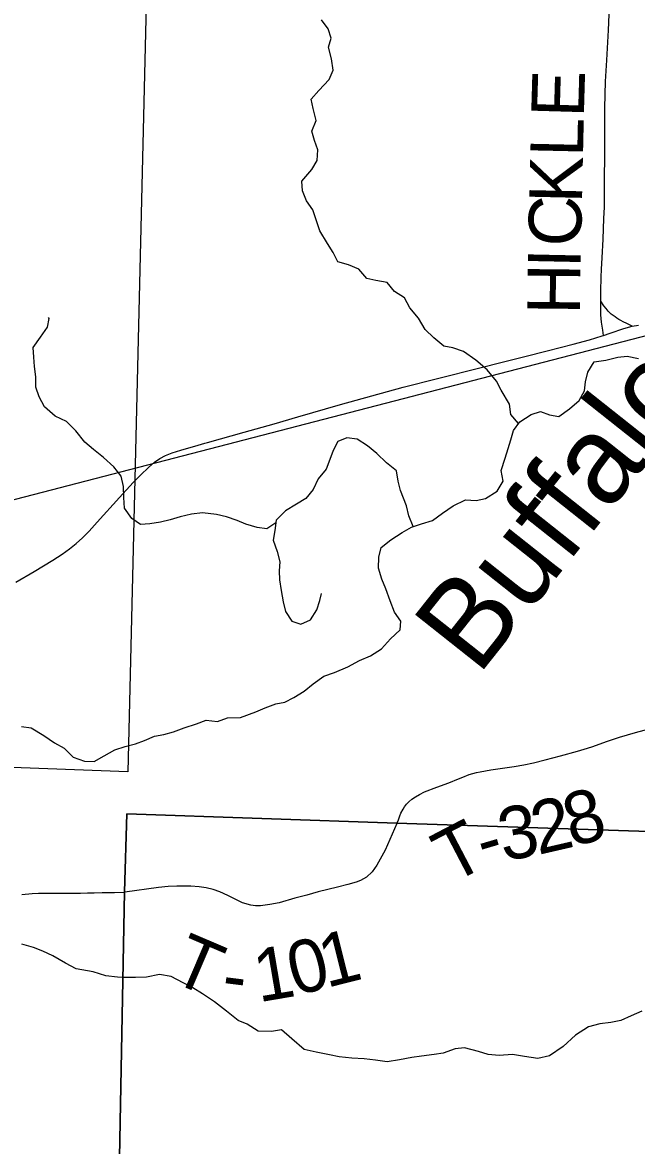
# Model space of a CAD drawing. Extents: x 0 to 34, y 0 to 22.
# Drawn here: x 26.994 to 27.656, y 18.296 to 19.507 of the extents above; entities that cross this region are included whole.
import ezdxf

# ---------------------------------------------------------------- set-up
doc = ezdxf.new("R2010")
doc.units = 0
for name, color, linetype in [('GM_X_Corporation', 7, 'Continuous'), ('GM_X_Minor_River', 7, 'Continuous'), ('GM_X_Minor_River_Text', 7, 'Continuous'), ('GM_X_Rail_Line', 7, 'Continuous'), ('GM_X_State_Route', 7, 'Continuous'), ('GM_X_Township_Road', 7, 'Continuous'), ('GM_X_Township_Road_Text', 7, 'Continuous')]:
    doc.layers.add(name, color=color, linetype=linetype)

msp = doc.modelspace()

# ---------------------------------------------------------------- linework, layer by layer
at = {"layer": 'GM_X_Corporation'}
for points in [[(26.6535, 14.621), (27.01, 14.6164), (27.046, 14.6155), (27.043, 14.755), (27.052, 15.403), (27.0676, 16.5549), (27.0694, 16.6556), (27.0775, 16.888), (27.0944, 18.0731), (27.1039, 18.5696), (27.1064, 18.6537), (27.3971, 18.6436), (28.3421, 18.6121), (28.7772, 18.6028), (29.0074, 18.5935), (29.6561, 18.5791), (29.6772, 18.5786), (30.101, 18.5701), (30.3167, 18.565), (30.3167, 20.9), (23.5167, 20.9)], [(26.3378, 16.673), (27.0694, 16.6556), (27.0775, 16.888), (27.0944, 18.0731), (27.1039, 18.5696), (27.1064, 18.6537), (27.3971, 18.6436), (28.3421, 18.6121), (28.7772, 18.6028), (29.0074, 18.5935), (29.6561, 18.5791), (29.6772, 18.5786), (30.101, 18.5701), (30.3167, 18.565), (30.3167, 20.9), (25.1014, 20.9)], [(23.5167, 14.1), (30.3167, 14.1), (30.3167, 18.565), (30.101, 18.5701), (29.6772, 18.5786), (29.6561, 18.5791), (29.0074, 18.5935), (28.7772, 18.6028), (28.3421, 18.6121), (27.3971, 18.6436), (27.1064, 18.6537), (27.1039, 18.5696), (27.0944, 18.0731), (27.0775, 16.888), (27.0694, 16.6556), (27.0676, 16.5549), (27.052, 15.403), (27.043, 14.755), (27.046, 14.6155), (27.01, 14.6164), (26.6535, 14.621)], [(30.3167, 14.5373), (30.3167, 18.565), (30.101, 18.5701), (29.6772, 18.5786), (29.6561, 18.5791), (29.0074, 18.5935), (28.7772, 18.6028), (28.3421, 18.6121), (27.3971, 18.6436), (27.1064, 18.6537), (27.1039, 18.5696), (27.0944, 18.0731)]]:
    msp.add_lwpolyline(points, dxfattribs=at)
msp.add_lwpolyline([(27.1321, 19.6957), (27.1305, 19.6616), (27.1072, 18.6988), (26.0916, 18.7368), (26.1009, 19.7362)], close=True, dxfattribs=at)
at = {"layer": 'GM_X_Minor_River'}
for points in [[(27.5284, 19.0744), (27.52, 19.0842), (27.5187, 19.0952), (27.5095, 19.1102), (27.5045, 19.12), (27.4946, 19.1324), (27.4824, 19.1429), (27.4691, 19.1522), (27.4577, 19.1559), (27.4479, 19.1577), (27.4372, 19.1667), (27.4277, 19.1757), (27.4204, 19.1881), (27.4112, 19.199), (27.4055, 19.2099), (27.3948, 19.2166), (27.3868, 19.2264), (27.3747, 19.2285), (27.3648, 19.2307), (27.3564, 19.2408), (27.3451, 19.2456), (27.3337, 19.2489), (27.3287, 19.2587), (27.3226, 19.2685), (27.3141, 19.2821), (27.3106, 19.293), (27.3067, 19.3047), (27.2999, 19.3145), (27.2956, 19.3254), (27.2948, 19.3356), (27.3056, 19.3483), (27.3112, 19.3582), (27.3122, 19.3696), (27.3084, 19.3797), (27.3056, 19.3896), (27.3104, 19.401), (27.3069, 19.4142), (27.3049, 19.424), (27.3132, 19.4336), (27.3244, 19.4455), (27.3285, 19.4554), (27.3269, 19.4675), (27.3237, 19.4803), (27.3263, 19.4898), (27.3232, 19.5), (27.3159, 19.5098)], [(27.267, 18.9674), (27.2572, 18.9609), (27.2466, 18.9623), (27.2345, 18.966), (27.225, 18.9697), (27.2136, 18.9737), (27.203, 18.9763), (27.1879, 18.978), (27.1758, 18.9767), (27.1637, 18.9739), (27.1528, 18.9704), (27.1426, 18.968), (27.1309, 18.9664), (27.1211, 18.9655), (27.1116, 18.9719), (27.1039, 18.9832), (27.1031, 18.9945), (27.1026, 19.0066), (27.1002, 19.0176), (27.0922, 19.0277), (27.0811, 19.0379), (27.0705, 19.0465), (27.061, 19.0543), (27.0514, 19.0667), (27.0411, 19.0765), (27.029, 19.0824), (27.0175, 19.0925), (27.0118, 19.1031), (27.0083, 19.1136), (27.0082, 19.1246), (27.0069, 19.136), (27.0061, 19.1458), (27.0053, 19.1564), (27.0131, 19.1675), (27.0206, 19.1782), (27.0224, 19.1877), (27.022, 19.1888)], [(27.0933, 18.7224), (27.1043, 18.7263), (27.1156, 18.7291), (27.1254, 18.7326), (27.1359, 18.7372), (27.1461, 18.7392), (27.1567, 18.742), (27.168, 18.7463), (27.1812, 18.7506), (27.1917, 18.7545), (27.2038, 18.7531), (27.2148, 18.757), (27.2287, 18.7575), (27.2453, 18.7634), (27.2555, 18.768), (27.2668, 18.7723), (27.2766, 18.774), (27.2864, 18.779), (27.2973, 18.7859), (27.307, 18.7936), (27.3187, 18.8021), (27.33, 18.806), (27.3443, 18.8122), (27.3571, 18.8188), (27.3688, 18.8238), (27.3808, 18.8315), (27.3905, 18.8422), (27.4007, 18.8518), (27.4017, 18.8613), (27.3948, 18.8711), (27.3902, 18.8831), (27.3855, 18.896), (27.3809, 18.9065), (27.3774, 18.9186), (27.3777, 18.9304), (27.3802, 18.9406), (27.3907, 18.9491), (27.4028, 18.9568), (27.4129, 18.9626), (27.4239, 18.9661), (27.4355, 18.97), (27.4464, 18.9777), (27.4581, 18.9858), (27.4713, 18.992), (27.4826, 18.9913), (27.4928, 18.9937), (27.5052, 19.0014), (27.5119, 19.0121), (27.5095, 19.0238), (27.514, 19.0371), (27.5173, 19.0474), (27.5202, 19.0569), (27.5228, 19.0668), (27.5299, 19.0763), (27.5419, 19.084), (27.5521, 19.0872), (27.5619, 19.0839), (27.5718, 19.0821), (27.5834, 19.0902), (27.5936, 19.0994), (27.5995, 19.1097), (27.6006, 19.1195), (27.6031, 19.1298), (27.6098, 19.1408), (27.6223, 19.1429), (27.6355, 19.146), (27.6453, 19.1469), (27.6578, 19.1444)], [(27.4149, 18.9632), (27.4102, 18.975), (27.4078, 18.9856), (27.4012, 19.0022), (27.3985, 19.0124), (27.3969, 19.0234), (27.3862, 19.032), (27.3756, 19.0421), (27.3657, 19.0503), (27.3546, 19.0574), (27.3433, 19.0588), (27.3335, 19.0549), (27.3287, 19.0454), (27.325, 19.0355), (27.3209, 19.0252), (27.3123, 19.0149), (27.3071, 19.0031), (27.2993, 18.9936), (27.2891, 18.9874), (27.2774, 18.9801), (27.2673, 18.9701), (27.2659, 18.9591), (27.2641, 18.9485), (27.2684, 18.9364), (27.2711, 18.9254), (27.2705, 18.9156), (27.2709, 18.9057), (27.2725, 18.8944), (27.2749, 18.8823), (27.2773, 18.8717), (27.2842, 18.8612), (27.2936, 18.8579), (27.3042, 18.8629), (27.3109, 18.8736), (27.3142, 18.8835), (27.316, 18.8911)], [(26.9929, 18.7478), (27.0032, 18.7461), (27.0168, 18.7379), (27.0283, 18.73), (27.0389, 18.7245), (27.0484, 18.7147), (27.0606, 18.7103), (27.0711, 18.71), (27.0817, 18.7162), (27.0933, 18.7224)], [(27.0963, 18.4775), (27.0836, 18.479), (27.0701, 18.4831), (27.0515, 18.4863), (27.0402, 18.4926), (27.0265, 18.5004), (27.0158, 18.5056), (27.0056, 18.5093), (26.9931, 18.5129)], [(27.6611, 18.4406), (27.6497, 18.4357), (27.6387, 18.4308), (27.6278, 18.4286), (27.616, 18.4271), (27.6039, 18.4237), (27.5896, 18.415), (27.5763, 18.4025), (27.5619, 18.3926), (27.549, 18.3896), (27.5347, 18.3919), (27.5218, 18.3942), (27.5075, 18.3931), (27.4957, 18.3939), (27.4851, 18.3973), (27.47, 18.4011), (27.4602, 18.4), (27.4473, 18.3954), (27.4375, 18.3939), (27.4239, 18.3924), (27.4133, 18.3909), (27.4001, 18.3883), (27.3868, 18.386), (27.3743, 18.3879), (27.3619, 18.3895), (27.3486, 18.3899), (27.335, 18.3914), (27.3248, 18.3937), (27.3104, 18.3964), (27.2972, 18.3994), (27.284, 18.4108), (27.2731, 18.4207), (27.2621, 18.4188), (27.2477, 18.4192), (27.236, 18.4268), (27.2262, 18.4306), (27.2137, 18.4408), (27.2009, 18.4507), (27.1877, 18.4594), (27.1775, 18.4659), (27.1669, 18.4712), (27.1541, 18.4781), (27.1416, 18.4804), (27.1276, 18.4773), (27.1155, 18.477), (27.103, 18.477), (27.0963, 18.4775)]]:
    msp.add_lwpolyline(points, dxfattribs=at)
at = {"layer": 'GM_X_Rail_Line'}
msp.add_lwpolyline([(28.8018, 19.5008), (28.2457, 19.3243), (28.1529, 19.2955), (27.3181, 19.0787), (26.8719, 18.963)], dxfattribs=at)
at = {"layer": 'GM_X_State_Route'}
msp.add_lwpolyline([(26.9866, 18.9032), (27.0064, 18.915), (27.0266, 18.9271), (27.0365, 18.9335), (27.0445, 18.9393), (27.0517, 18.9451), (27.0586, 18.9513), (27.0656, 18.9583), (27.0744, 18.9679), (27.0984, 18.9948), (27.1131, 19.0108), (27.1209, 19.0188), (27.1299, 19.0275), (27.1361, 19.0328), (27.1418, 19.0367), (27.148, 19.04), (27.155, 19.0427), (27.1644, 19.0458), (27.183, 19.051), (27.1902, 19.0531), (27.1932, 19.054), (27.2326, 19.0651), (27.2649, 19.0742), (27.2906, 19.0815), (27.3366, 19.0949), (27.4042, 19.1137), (27.441, 19.1231), (27.4868, 19.1344), (27.5109, 19.1404), (27.535, 19.1466), (27.5591, 19.1527), (27.5874, 19.1598), (27.6048, 19.1646), (27.6184, 19.1688), (27.6198, 19.1693), (27.6272, 19.1718), (27.6419, 19.1769), (27.6507, 19.1793), (27.6577, 19.1806)], dxfattribs=at)
at = {"layer": 'GM_X_Township_Road'}
for points in [[(27.6169, 19.2065), (27.6169, 19.2172), (27.6174, 19.2321), (27.6179, 19.2408), (27.6184, 19.2532), (27.6196, 19.2731), (27.6204, 19.2954), (27.6209, 19.3078), (27.6211, 19.3265), (27.6213, 19.375), (27.6214, 19.3893), (27.6215, 19.4147), (27.6222, 19.4433), (27.6234, 19.4663), (27.6252, 19.4986), (27.6268, 19.5327)], [(27.6198, 19.1693), (27.6191, 19.1749), (27.6179, 19.1836), (27.6172, 19.1917), (27.6169, 19.2023), (27.6169, 19.2065)], [(27.6507, 19.1793), (27.6451, 19.1822), (27.6413, 19.1842), (27.6388, 19.1855), (27.6365, 19.1867), (27.6344, 19.1879), (27.6324, 19.1893), (27.6303, 19.1908), (27.6283, 19.1924), (27.6251, 19.1955), (27.6227, 19.1983), (27.6204, 19.2014), (27.6169, 19.2065)], [(27.3973, 18.6431), (27.3989, 18.6472), (27.4006, 18.6512), (27.4017, 18.6541), (27.4039, 18.6584), (27.4055, 18.661), (27.4077, 18.6638), (27.4102, 18.6664), (27.4134, 18.6692), (27.4174, 18.672), (27.4217, 18.6744), (27.4272, 18.6771), (27.4405, 18.6823), (27.4492, 18.6856), (27.455, 18.6878), (27.4619, 18.6906), (27.4682, 18.6931), (27.4751, 18.6958), (27.4792, 18.6971), (27.483, 18.698), (27.487, 18.6989), (27.4985, 18.701), (27.5236, 18.7047), (27.534, 18.7064), (27.5444, 18.7085), (27.557, 18.7116), (27.5736, 18.7161), (27.592, 18.7211), (27.6027, 18.7242), (27.6084, 18.7262), (27.623, 18.7314), (27.6371, 18.7361), (27.6543, 18.7413), (27.6693, 18.7453)], [(27.3973, 18.6431), (27.3847, 18.6142), (27.3755, 18.598), (27.3706, 18.5909), (27.3644, 18.5851), (27.358, 18.5816), (27.3534, 18.5797), (27.3444, 18.5772), (27.3332, 18.5743), (27.3228, 18.5719), (27.3125, 18.5693), (27.3002, 18.5659), (27.2873, 18.5625), (27.2704, 18.5577), (27.2603, 18.5557), (27.2503, 18.5544), (27.245, 18.5543), (27.2398, 18.5549), (27.231, 18.5575), (27.2236, 18.561), (27.2151, 18.5656), (27.2064, 18.5695), (27.1994, 18.572), (27.1919, 18.5738), (27.1843, 18.5749), (27.1754, 18.5755), (27.1603, 18.5755), (27.1509, 18.5752), (27.1404, 18.5742), (27.1041, 18.569)], [(26.993, 18.5667), (27.0042, 18.5676), (27.011, 18.5679), (27.0264, 18.5681), (27.0457, 18.568), (27.0562, 18.5681), (27.0637, 18.5682), (27.0711, 18.5683), (27.0797, 18.5686), (27.0832, 18.5686), (27.0867, 18.5686), (27.093, 18.5686), (27.1041, 18.569)]]:
    msp.add_lwpolyline(points, dxfattribs=at)

# ---------------------------------------------------------------- texts
at = {"layer": 'GM_X_Minor_River_Text'}
msp.add_text('Buffalo', height=0.09469, rotation=51.577, dxfattribs=at).set_placement((27.4847, 18.8013))
at = {"layer": 'GM_X_Township_Road_Text'}
for s, rotation, p in [('E', 88.3369, (27.5987, 19.4039)), ('L', 88.7271, (27.5978, 19.3615)), ('K', 88.7395, (27.5967, 19.3115)), ('C', 88.7431, (27.5956, 19.2648)), ('I', 88.79, (27.5951, 19.2415)), ('H', 89.3625, (27.5946, 19.1917)), ('8', 15.1423, (27.5857, 18.6175)), ('3', 10.2092, (27.512, 18.6023)), ('2', 13.0062, (27.5494, 18.6091)), ('T', 27.5751, (27.4562, 18.5775)), ('-', 16.3598, (27.4912, 18.5961)), ('T', 336.8695, (27.1513, 18.4739)), ('0', 14.1375, (27.2875, 18.4571)), ('1', 14.1395, (27.3214, 18.4657)), ('1', 9.6725, (27.2483, 18.4502)), ('-', 352.9181, (27.2071, 18.4527))]:
    msp.add_text(s, height=0.0568, rotation=rotation, dxfattribs=at).set_placement(p)

doc.saveas('drawing.dxf')
